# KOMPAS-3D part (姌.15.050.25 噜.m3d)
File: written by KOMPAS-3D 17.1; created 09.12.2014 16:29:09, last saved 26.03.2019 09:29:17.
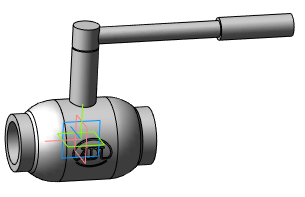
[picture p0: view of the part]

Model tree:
1. Операция без истории:6  (labels: Сталь 20  ГОСТ 1050-88)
